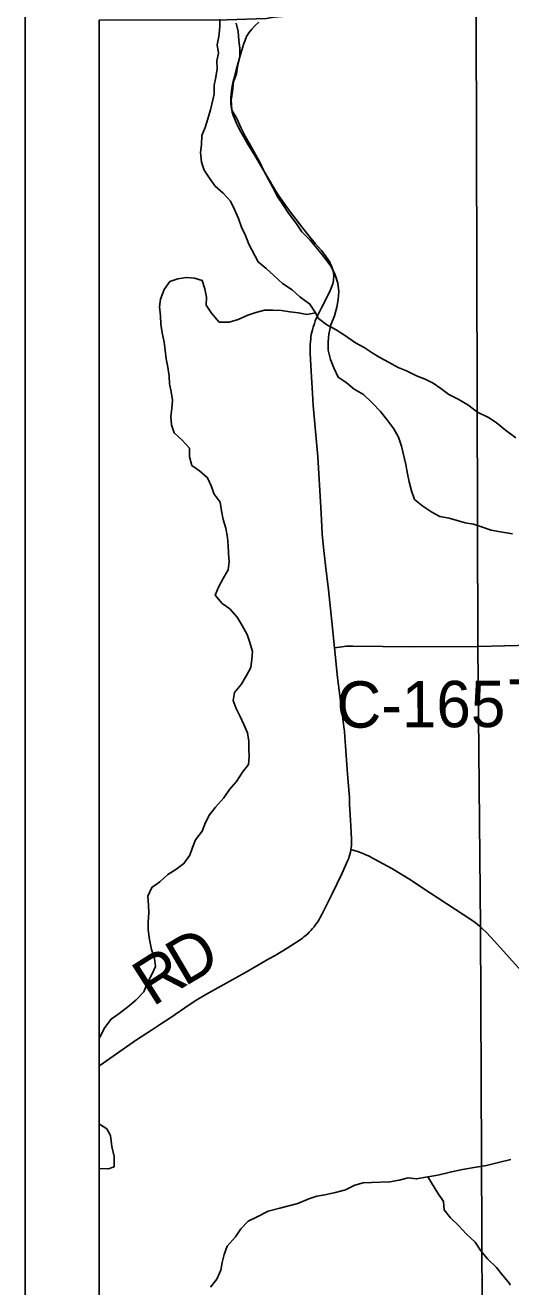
# Model space of a CAD drawing. Extents: x 0 to 34, y 0 to 22.
# Drawn here: x 12.556 to 13.151, y 11.106 to 12.652 of the extents above; entities that cross this region are included whole.
import ezdxf

# ---------------------------------------------------------------- set-up
doc = ezdxf.new("R2010")
doc.units = 0
for name, color, linetype in [('GM_X_Corporation', 7, 'Continuous'), ('GM_X_County_Road', 7, 'Continuous'), ('GM_X_County_Road_Text', 7, 'Continuous'), ('GM_X_Major_Lake', 7, 'Continuous'), ('GM_X_Minor_Lake', 7, 'Continuous'), ('GM_X_Minor_River', 7, 'Continuous'), ('GM_X_Township_Road', 7, 'Continuous'), ('GM_X_Township_Road_Text', 7, 'Continuous'), ('SH_Data', 7, 'Continuous')]:
    doc.layers.add(name, color=color, linetype=linetype)

msp = doc.modelspace()

# ---------------------------------------------------------------- linework, layer by layer
at = {"layer": 'GM_X_Corporation'}
msp.add_lwpolyline([(12.6467, 12.6578), (12.6467, 9.9214), (13.1219, 9.9214), (13.1218, 9.9288), (13.1204, 10.132), (13.114, 11.5469), (13.111, 11.8906), (13.1086, 12.6609), (13.1086, 12.6624), (13.1076, 12.6624), (13.0548, 12.663), (12.9541, 12.6637), (12.9314, 12.6639), (12.9165, 12.6638), (12.8885, 12.6634), (12.8709, 12.6624), (12.8616, 12.6617), (12.856, 12.6608), (12.8517, 12.6598), (12.8032, 12.6583)], close=True, dxfattribs=at)
msp.add_lwpolyline([(13.1086, 12.6609), (13.111, 11.8906), (13.114, 11.5469), (13.1204, 10.132), (13.1218, 9.9288), (13.1219, 9.9214), (18.7033, 9.9214)], dxfattribs=at)
at = {"layer": 'GM_X_County_Road'}
for points in [[(12.9351, 11.8887), (12.9317, 11.9208), (12.9276, 11.9597), (12.9242, 11.9899), (12.9217, 12.0115), (12.9201, 12.0282), (12.919, 12.0456), (12.9183, 12.0605), (12.9148, 12.1225), (12.9091, 12.1854), (12.908, 12.2002), (12.9066, 12.2275), (12.9053, 12.2493), (12.9053, 12.2534), (12.9052, 12.2574), (12.9053, 12.2604), (12.9055, 12.2637), (12.9059, 12.2672), (12.9062, 12.2699), (12.9067, 12.2726), (12.9073, 12.2755), (12.908, 12.2782), (12.9089, 12.2815), (12.9104, 12.2859), (12.9116, 12.2892), (12.9132, 12.293), (12.9145, 12.2961), (12.9194, 12.3062), (12.9296, 12.3261), (12.9316, 12.3306), (12.9323, 12.3328), (12.9329, 12.3347), (12.9334, 12.3368), (12.9338, 12.3388), (12.934, 12.341), (12.9342, 12.343), (12.9341, 12.3451), (12.934, 12.3472), (12.9334, 12.3508), (12.9324, 12.3543), (12.9311, 12.3577), (12.9298, 12.3601), (12.9288, 12.362), (12.9268, 12.365), (12.9251, 12.3676), (12.9191, 12.3754), (12.912, 12.3838), (12.9041, 12.393), (12.8965, 12.4028), (12.8798, 12.4243), (12.8724, 12.4343), (12.869, 12.4395), (12.8662, 12.4436), (12.862, 12.4504), (12.8594, 12.4546), (12.8374, 12.4919), (12.829, 12.5059), (12.8204, 12.521), (12.8155, 12.5304), (12.8124, 12.5372), (12.8114, 12.54), (12.8104, 12.5425), (12.8098, 12.5449), (12.8091, 12.5474), (12.8088, 12.5495), (12.8083, 12.5523), (12.8081, 12.5552), (12.808, 12.5574), (12.808, 12.5602), (12.8081, 12.563), (12.8085, 12.5671), (12.8088, 12.5714), (12.8093, 12.5742), (12.8097, 12.5769), (12.8106, 12.5809), (12.8117, 12.5855), (12.815, 12.5981), (12.819, 12.6131), (12.8239, 12.6293), (12.825, 12.6321), (12.8259, 12.6345), (12.8269, 12.6366), (12.8278, 12.6385), (12.8289, 12.6404), (12.8301, 12.6423), (12.8337, 12.6468), (12.8379, 12.6513), (12.8425, 12.6553)], [(12.9351, 11.8887), (12.9443, 11.89), (12.9469, 11.8903), (12.9495, 11.8905), (12.9523, 11.8907), (12.9582, 11.8907), (13.0308, 11.89), (13.1112, 11.8901)], [(12.9552, 11.6413), (12.9557, 11.6437), (12.9559, 11.646), (12.956, 11.6485), (12.956, 11.651), (12.956, 11.654), (12.9555, 11.6626), (12.9548, 11.6775), (12.9536, 11.6967), (12.9533, 11.7054), (12.952, 11.7239), (12.9505, 11.7393), (12.948, 11.774), (12.9476, 11.7793), (12.9472, 11.7864), (12.9466, 11.7913), (12.9461, 11.7956), (12.9415, 11.8301), (12.9389, 11.8523), (12.9351, 11.8887)], [(12.6467, 11.3761), (12.6476, 11.3768), (12.68, 11.3997), (12.6922, 11.4081), (12.7108, 11.4201), (12.722, 11.4273), (12.7345, 11.4357), (12.757, 11.4512), (12.7665, 11.4573), (12.7774, 11.4636), (12.825, 11.4903), (12.8546, 11.5073), (12.8622, 11.5116), (12.8771, 11.5205), (12.8932, 11.5309), (12.8958, 11.5328), (12.8977, 11.5342), (12.9002, 11.5364), (12.9024, 11.5382), (12.9042, 11.5401), (12.9062, 11.5421), (12.9083, 11.5446), (12.9102, 11.5468), (12.9122, 11.5498), (12.9145, 11.5528), (12.9162, 11.5556), (12.9177, 11.5581), (12.9196, 11.5616), (12.9218, 11.5657), (12.9322, 11.5869), (12.944, 11.6116), (12.9516, 11.6283), (12.9525, 11.6309), (12.9532, 11.6329), (12.9539, 11.6355), (12.9546, 11.6382), (12.9552, 11.6413)], [(13.1142, 11.5464), (13.1125, 11.5479), (13.1074, 11.5519), (13.1036, 11.5547), (13.0421, 11.5949), (13.0281, 11.6042), (13.017, 11.6111), (13.0053, 11.618), (12.9843, 11.6295), (12.9806, 11.6315), (12.9767, 11.6335), (12.9744, 11.6346), (12.9717, 11.6357), (12.9679, 11.6374), (12.9656, 11.6382), (12.9626, 11.6392), (12.9604, 11.64), (12.958, 11.6406), (12.9552, 11.6413)], [(13.1677, 11.4885), (13.1313, 11.529), (13.1213, 11.5397), (13.116, 11.5448), (13.1151, 11.5456), (13.1142, 11.5464)]]:
    msp.add_lwpolyline(points, dxfattribs=at)
at = {"layer": 'GM_X_Major_Lake'}
for points in [[(12.7262, 12.3277), (12.7333, 12.3377), (12.7431, 12.3408), (12.7537, 12.3424), (12.7635, 12.3417), (12.773, 12.3387), (12.7761, 12.3285), (12.7781, 12.3183), (12.7778, 12.3084), (12.7843, 12.2986), (12.7939, 12.2877), (12.806, 12.2878), (12.8169, 12.2909), (12.829, 12.2963), (12.8388, 12.2994), (12.8494, 12.3025), (12.86, 12.3026), (12.8702, 12.3019), (12.8804, 12.3005), (12.891, 12.2991), (12.9013, 12.2972), (12.9119, 12.2992), (12.905, 12.3098), (12.8928, 12.3188), (12.8833, 12.3274), (12.8715, 12.3353), (12.8608, 12.3451), (12.8513, 12.3534), (12.8417, 12.3616), (12.8302, 12.3835), (12.826, 12.3941), (12.8213, 12.4043), (12.8175, 12.4149), (12.8125, 12.4259), (12.8078, 12.4361), (12.7987, 12.4459), (12.7888, 12.4545), (12.7819, 12.4643), (12.7754, 12.4741), (12.7719, 12.4839), (12.771, 12.4957), (12.7721, 12.5052), (12.7724, 12.5166), (12.7765, 12.5265), (12.7798, 12.5371), (12.7831, 12.5481), (12.7875, 12.5671), (12.7878, 12.5781), (12.7896, 12.588), (12.7914, 12.5982), (12.791, 12.6081), (12.7928, 12.6176), (12.7912, 12.6278), (12.7934, 12.6377), (12.7944, 12.6495), (12.7944, 12.6589)], [(12.6467, 11.4104), (12.6479, 11.4121), (12.6534, 11.4232), (12.6613, 11.4335), (12.6711, 11.4404), (12.6813, 11.4484), (12.6914, 11.4568), (12.7015, 11.4668), (12.7049, 11.4763), (12.7112, 11.4881), (12.7157, 11.498), (12.7145, 11.5078), (12.7106, 11.5188), (12.7082, 11.5313), (12.7066, 11.543), (12.7065, 11.5529), (12.7076, 11.5639), (12.7071, 11.5734), (12.7063, 11.5844), (12.7111, 11.595), (12.7209, 11.6019), (12.7307, 11.6107), (12.7405, 11.6168), (12.7506, 11.6241), (12.7578, 11.6344), (12.7611, 11.6439), (12.7648, 11.6534), (12.7727, 11.6637), (12.7771, 11.6744), (12.782, 11.6839), (12.7891, 11.6934), (12.7996, 11.7049), (12.8063, 11.7148), (12.8149, 11.7247), (12.8224, 11.7362), (12.8295, 11.7457), (12.8306, 11.7552), (12.8302, 11.7647), (12.8301, 11.7741), (12.8285, 11.7844), (12.8239, 11.7946), (12.8196, 11.8044), (12.8146, 11.8142), (12.8108, 11.8241), (12.8126, 11.8339), (12.8208, 11.8435), (12.8272, 11.8545), (12.8324, 11.8644), (12.8338, 11.8747), (12.8345, 11.8841), (12.8314, 11.8951), (12.8279, 11.905), (12.8218, 11.9159), (12.816, 11.9261), (12.8068, 11.9363), (12.7973, 11.943), (12.7889, 11.9532), (12.793, 11.9631), (12.7986, 11.9737), (12.8046, 11.984), (12.806, 11.9939), (12.8052, 12.0045), (12.8047, 12.014), (12.8039, 12.0238), (12.8019, 12.0352), (12.7988, 12.0458), (12.7964, 12.0564), (12.7948, 12.067), (12.7876, 12.0768), (12.7841, 12.087), (12.7795, 12.0968), (12.7696, 12.1055), (12.7601, 12.1122), (12.7573, 12.1228), (12.7572, 12.1331), (12.7485, 12.1429), (12.7385, 12.1519), (12.7354, 12.1617), (12.7346, 12.1723), (12.7357, 12.1818), (12.7367, 12.1921), (12.7347, 12.2023), (12.7328, 12.2121), (12.7323, 12.2216), (12.7307, 12.2326), (12.7287, 12.2428), (12.7275, 12.2534), (12.7263, 12.2633), (12.724, 12.2746), (12.7224, 12.2852), (12.7219, 12.2955), (12.7207, 12.3065), (12.7217, 12.3159), (12.7262, 12.3277)]]:
    msp.add_lwpolyline(points, dxfattribs=at)
at = {"layer": 'GM_X_Minor_Lake'}
msp.add_lwpolyline([(12.6467, 11.2505), (12.6469, 11.2506), (12.6582, 11.2499), (12.665, 11.2526), (12.6649, 11.2651), (12.6622, 11.2776), (12.6605, 11.2909), (12.6559, 11.2992), (12.6472, 11.3048), (12.6467, 11.3048)], dxfattribs=at)
at = {"layer": 'GM_X_Minor_River'}
for points in [[(12.8649, 12.4422), (12.8596, 12.4528), (12.8542, 12.4626), (12.8484, 12.4732), (12.8438, 12.483), (12.8384, 12.4932), (12.8319, 12.5049), (12.8258, 12.5155), (12.8204, 12.5264), (12.8154, 12.5374), (12.8092, 12.5476), (12.8084, 12.5597), (12.8102, 12.5703), (12.8112, 12.5821), (12.815, 12.592), (12.8168, 12.6034), (12.819, 12.6129), (12.8189, 12.6231), (12.8177, 12.6333), (12.8172, 12.644), (12.8145, 12.6542)], [(13.1532, 12.0284), (13.1388, 12.0306), (13.127, 12.0328), (13.1153, 12.0369), (13.1054, 12.0402), (13.0955, 12.0416), (13.0758, 12.0476), (13.0641, 12.0494), (13.0546, 12.055), (13.0435, 12.0621), (13.0333, 12.0704), (13.0294, 12.0809), (13.0267, 12.0919), (13.0247, 12.1018), (13.0227, 12.1131), (13.0172, 12.1358), (13.0134, 12.1468), (13.008, 12.157), (12.9992, 12.1683), (12.9915, 12.1781), (12.9812, 12.189), (12.9706, 12.1992), (12.9591, 12.2055), (12.9496, 12.2138), (12.9397, 12.2202), (12.9343, 12.2319), (12.9301, 12.2421), (12.9274, 12.2534), (12.9273, 12.2637), (12.928, 12.2732), (12.9305, 12.2846), (12.935, 12.2956), (12.9379, 12.3059), (12.9397, 12.3154), (12.9404, 12.3252), (12.9392, 12.3354), (12.9361, 12.3457), (12.9311, 12.3559), (12.9219, 12.3676), (12.9135, 12.3785), (12.9051, 12.3883), (12.8952, 12.3984), (12.8879, 12.4094), (12.8787, 12.4214), (12.8718, 12.432), (12.8649, 12.4422)], [(13.1576, 12.146), (13.1446, 12.1554), (13.1332, 12.1648), (13.1237, 12.1708), (13.1104, 12.1775), (13.0986, 12.1865), (13.0868, 12.1932), (13.0754, 12.1992), (13.0655, 12.2064), (13.056, 12.2131), (13.0461, 12.218), (13.0355, 12.2221), (13.0233, 12.228), (13.0131, 12.2321), (13.0013, 12.2388), (12.9906, 12.2445), (12.9811, 12.2501), (12.9716, 12.2568), (12.961, 12.2624), (12.9484, 12.2711), (12.937, 12.2782), (12.9256, 12.2845), (12.9153, 12.2924), (12.9119, 12.2992)], [(12.7831, 11.1049), (12.791, 11.1148), (12.7958, 11.1258), (12.7976, 11.1353), (12.7998, 11.1452), (12.8035, 11.1551), (12.8137, 11.1669), (12.8204, 11.1765), (12.8294, 11.186), (12.8403, 11.1914), (12.8539, 11.198), (12.8683, 11.2019), (12.8792, 11.2046), (12.8902, 11.2077), (12.9038, 11.2131), (12.9136, 11.2166), (12.9234, 11.2182), (12.9362, 11.221), (12.9487, 11.2245), (12.96, 11.2299), (12.9702, 11.233), (12.9804, 11.2335), (13.0028, 11.234), (13.0145, 11.236), (13.0254, 11.2391), (13.0353, 11.2377), (13.0496, 11.2404), (13.0617, 11.2424), (13.0768, 11.246), (13.092, 11.2491), (13.1063, 11.2519), (13.1214, 11.2543), (13.1362, 11.2578), (13.1513, 11.2617)], [(13.0496, 11.2404), (13.0619, 11.2201), (13.0688, 11.2099), (13.0696, 11.2), (13.0773, 11.1902), (13.0876, 11.1804), (13.0967, 11.1703), (13.1074, 11.1601), (13.1147, 11.1496), (13.1227, 11.1398), (13.1338, 11.1292), (13.1414, 11.1194), (13.1502, 11.1093), (13.1502, 11.1074)]]:
    msp.add_lwpolyline(points, dxfattribs=at)
at = {"layer": 'GM_X_Township_Road'}
msp.add_lwpolyline([(13.1112, 11.8901), (13.176, 11.892), (13.1992, 11.8923), (13.2407, 11.8924), (13.2675, 11.8922), (13.2832, 11.8922), (13.2983, 11.8922), (13.3371, 11.8924), (13.4214, 11.8922), (13.5238, 11.8917), (13.5377, 11.8917), (13.5555, 11.8918), (13.5644, 11.8919), (13.5753, 11.892), (13.5773, 11.892)], dxfattribs=at)
at = {"layer": 'SH_Data'}
msp.add_line((12.556, 16.8098), (12.556, 9.8098), dxfattribs=at)

# ---------------------------------------------------------------- texts
at = {"layer": 'GM_X_County_Road_Text'}
for s, height, rotation, p in [('C-165', 0.05682, 0.2768, (12.9377, 11.7906)), ('D', 0.0568, 30.434, (12.7511, 11.4729)), ('R', 0.0568, 32.5014, (12.7122, 11.4481))]:
    msp.add_text(s, height=height, rotation=rotation, dxfattribs=at).set_placement(p)
at = {"layer": 'GM_X_Township_Road_Text'}
msp.add_text('T-165', height=0.05682, rotation=0.2739, dxfattribs=at).set_placement((13.1486, 11.7932))

doc.saveas('drawing.dxf')
